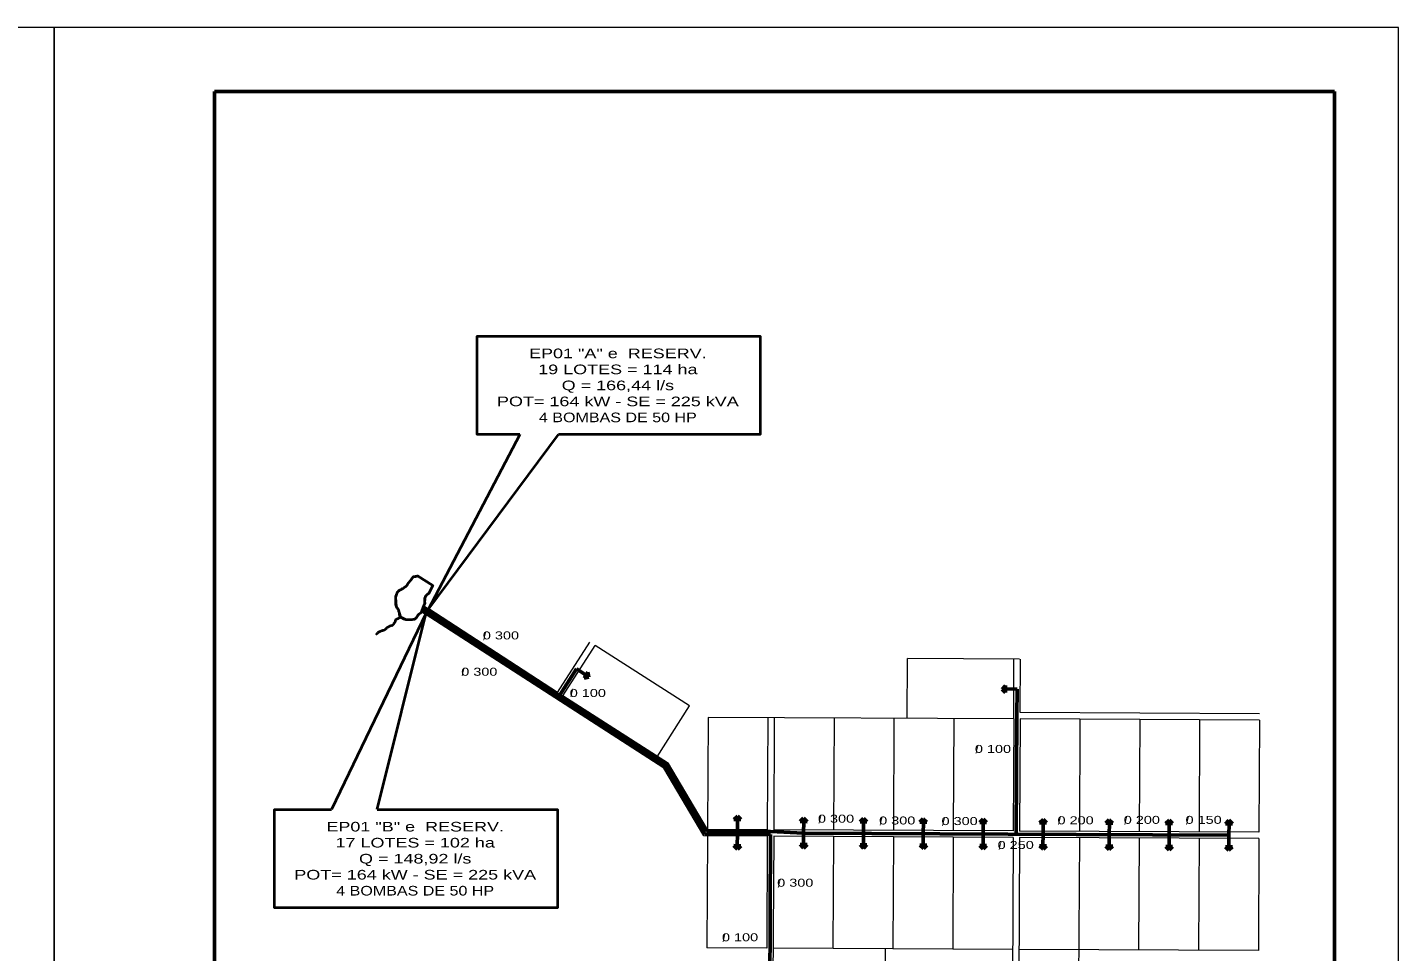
# Model space of a CAD drawing. Extents: x 312964 to 351929, y 9004151 to 9034973.
# Drawn here: x 347467 to 351751, y 9016114 to 9019001 of the extents above; entities that cross this region are included whole.
import ezdxf
from ezdxf.enums import TextEntityAlignment as Align

# ---------------------------------------------------------------- set-up
doc = ezdxf.new("R2010")
doc.units = 0
doc.header["$LTSCALE"] = 10
doc.layers.add('1', color=7, linetype='Continuous', lineweight=13)
doc.layers.add('2', color=7, linetype='Continuous', lineweight=53)

msp = doc.modelspace()

# ---------------------------------------------------------------- linework, layer by layer
at = {"layer": '1', "lineweight": 53}
for p, q in [((348050.92, 9018801.07), (348050.92, 9013261.07)), ((351550.92, 9018801.07), (348050.92, 9018801.07)), ((351550.92, 9013261.07), (351550.92, 9018801.07)), ((349137.41, 9016908.55), (348717.87, 9017180.57)), ((349132.01, 9016900.13), (348712.47, 9017172.15)), ((349128.99, 9016913.95), (349182.16, 9016996.86)), ((349212.23, 9016977.34), (349182.16, 9016996.86)), ((349206.5, 9016968.52), (349218.24, 9016986.6)), ((349221.41, 9016971.68), (349206.5, 9016968.52)), ((349221.41, 9016971.68), (349218.24, 9016986.6)), ((350512.16, 9016934.25), (350522.99, 9016944.98)), ((350512.16, 9016934.25), (350522.89, 9016923.42)), ((350522.99, 9016944.98), (350522.89, 9016923.42)), ((350522.94, 9016934.45), (350558.79, 9016934.28)), ((350558.38, 9016850.78), (350558.79, 9016934.28)), ((349466.48, 9016697.51), (349137.41, 9016908.55)), ((350558.38, 9016850.78), (350556.57, 9016480.78)), ((349588.76, 9016490.53), (349466.48, 9016697.51)), ((349685.08, 9016537.25), (349674.24, 9016526.52)), ((349685.08, 9016537.25), (349695.8, 9016526.42)), ((349695.8, 9016526.42), (349674.24, 9016526.52)), ((349685.28, 9016526.47), (349685.1, 9016490.62)), ((349892.05, 9016530.67), (349881.21, 9016519.94)), ((349902.77, 9016519.84), (349881.21, 9016519.94)), ((349892.05, 9016530.67), (349902.77, 9016519.84)), ((349892.25, 9016519.89), (349892.07, 9016484.04)), ((350079.04, 9016529.75), (350068.21, 9016519.03)), ((350089.77, 9016518.92), (350068.21, 9016519.03)), ((350079.04, 9016529.75), (350089.77, 9016518.92)), ((350079.25, 9016518.97), (350079.07, 9016483.12)), ((350266.04, 9016528.84), (350255.21, 9016518.11)), ((350276.77, 9016518), (350255.21, 9016518.11)), ((350266.04, 9016528.84), (350276.77, 9016518)), ((350266.25, 9016518.06), (350266.07, 9016482.21)), ((350453.04, 9016527.92), (350442.21, 9016517.19)), ((350463.76, 9016517.09), (350442.21, 9016517.19)), ((350453.04, 9016527.92), (350463.76, 9016517.09)), ((350453.24, 9016517.14), (350453.07, 9016481.29)), ((350640.04, 9016527), (350629.2, 9016516.28)), ((350650.76, 9016516.17), (350629.2, 9016516.28)), ((350640.04, 9016527), (350650.76, 9016516.17)), ((350640.24, 9016516.22), (350640.06, 9016480.37)), ((350847.03, 9016525.99), (350836.2, 9016515.26)), ((350857.76, 9016515.15), (350836.2, 9016515.26)), ((350847.03, 9016525.99), (350857.76, 9016515.15)), ((350847.24, 9016515.21), (350847.06, 9016479.36)), ((351034.03, 9016525.07), (351023.2, 9016514.34)), ((351044.76, 9016514.24), (351023.2, 9016514.34)), ((351034.03, 9016525.07), (351044.76, 9016514.24)), ((351034.24, 9016514.29), (351034.06, 9016478.44)), ((351221.03, 9016524.15), (351210.2, 9016513.43)), ((351231.76, 9016513.32), (351210.2, 9016513.43)), ((351221.03, 9016524.15), (351231.76, 9016513.32)), ((351221.24, 9016513.37), (351221.06, 9016477.53)), ((349788.55, 9016479.55), (349583.04, 9016480.56)), ((349788.6, 9016489.55), (349588.76, 9016490.53)), ((349684.88, 9016444.93), (349685.06, 9016480.78)), ((349892.07, 9016484.04), (349788.6, 9016489.55)), ((349891.9, 9016448.19), (349892.07, 9016484.04)), ((350743.56, 9016479.87), (349892.07, 9016484.04)), ((350078.89, 9016447.28), (350079.07, 9016483.12)), ((350265.89, 9016446.36), (350266.07, 9016482.21)), ((350452.89, 9016445.44), (350453.07, 9016481.29)), ((350639.89, 9016444.53), (350640.06, 9016480.37)), ((351221.06, 9016477.53), (350743.56, 9016479.87)), ((350846.89, 9016443.51), (350847.06, 9016479.36)), ((351033.88, 9016442.59), (351034.06, 9016478.44)), ((351220.88, 9016441.68), (351221.06, 9016477.53)), ((349674.36, 9016444.98), (349695.92, 9016444.87)), ((349685.08, 9016434.15), (349674.36, 9016444.98)), ((349685.08, 9016434.15), (349695.92, 9016444.87)), ((349881.38, 9016448.24), (349902.93, 9016448.14)), ((349892.1, 9016437.41), (349881.38, 9016448.24)), ((349892.1, 9016437.41), (349902.93, 9016448.14)), ((350068.37, 9016447.33), (350089.93, 9016447.22)), ((350079.1, 9016436.5), (350068.37, 9016447.33)), ((350079.1, 9016436.5), (350089.93, 9016447.22)), ((350255.37, 9016446.41), (350276.93, 9016446.3)), ((350266.1, 9016435.58), (350255.37, 9016446.41)), ((350266.1, 9016435.58), (350276.93, 9016446.3)), ((350442.37, 9016445.49), (350463.93, 9016445.39)), ((350453.1, 9016434.66), (350442.37, 9016445.49)), ((350453.1, 9016434.66), (350463.93, 9016445.39)), ((350629.37, 9016444.58), (350650.93, 9016444.47)), ((350640.09, 9016433.75), (350629.37, 9016444.58)), ((350640.09, 9016433.75), (350650.93, 9016444.47)), ((350836.36, 9016443.56), (350857.92, 9016443.46)), ((350847.09, 9016432.73), (350836.36, 9016443.56)), ((350847.09, 9016432.73), (350857.92, 9016443.46)), ((351023.36, 9016442.65), (351044.92, 9016442.54)), ((351034.09, 9016431.81), (351023.36, 9016442.65)), ((351034.09, 9016431.81), (351044.92, 9016442.54)), ((351210.36, 9016441.73), (351231.92, 9016441.62)), ((351221.09, 9016430.9), (351210.36, 9016441.73)), ((351221.09, 9016430.9), (351231.92, 9016441.62))]:
    msp.add_line(p, q, dxfattribs=at)
at = {"layer": '1', "lineweight": 40}
for p, q in [((348686.16, 9017287.63), (348733.17, 9017257.22)), ((348698.47, 9017177.95), (348719.14, 9017182.72)), ((348706.42, 9017190.67), (348711.2, 9017170)), ((348712.43, 9017171.97), (348720.37, 9017184.7))]:
    msp.add_line(p, q, dxfattribs=at)
at = {"layer": '1'}
for points in [[(343350.92, 9019001.07), (343350.92, 9013061.07), (347550.92, 9013061.07), (347550.92, 9019001.07)], [(347550.92, 9019001.07), (347550.92, 9013061.07), (351750.92, 9013061.07), (351750.92, 9019001.07)]]:
    msp.add_lwpolyline(points, close=True, dxfattribs=at)
at = {"layer": '1', "lineweight": 40}
for points in [[(348633.15, 9017158.29), (348627.76, 9017179.39), (348620.03, 9017191.34), (348618.16, 9017221.59), (348623.08, 9017236.59), (348631.04, 9017244.56), (348636.66, 9017246.44), (348651.65, 9017256.28), (348661.73, 9017270.58), (348673.67, 9017285.82), (348686.16, 9017287.63), (348733.17, 9017257.22), (348720.05, 9017231.9), (348716.77, 9017230.49), (348709.75, 9017222.06), (348707.87, 9017206.35), (348707.4, 9017199.08), (348704.59, 9017193.92), (348696.16, 9017171.89), (348688.43, 9017166.96), (348681.4, 9017156.18), (348675.31, 9017151.73), (348657.74, 9017150.32), (348647.91, 9017151.26)], [(348711.2, 9017170), (348719.14, 9017182.72), (348706.42, 9017190.67), (348698.47, 9017177.95)]]:
    msp.add_lwpolyline(points, close=True, dxfattribs=at)
for points in [[(348653.53, 9017258.63), (348653.53, 9017259.1), (348654, 9017260.03), (348654, 9017260.97), (348654.93, 9017261.91), (348655.4, 9017263.32), (348655.87, 9017263.32), (348656.34, 9017264.25), (348656.34, 9017264.72), (348656.81, 9017264.72), (348657.74, 9017266.13), (348660.56, 9017268.94), (348662.9, 9017272.22), (348666.65, 9017276.44), (348669.46, 9017280.19), (348670.86, 9017283.01), (348672.27, 9017284.41), (348672.74, 9017285.35), (348673.2, 9017285.82), (348673.67, 9017285.82), (348674.14, 9017285.82), (348676.02, 9017285.82), (348679.3, 9017286.29), (348683.98, 9017286.76), (348686.16, 9017287.63)], [(348689.13, 9017167.2), (348687.73, 9017166.73), (348687.26, 9017165.79), (348686.32, 9017164.85), (348684.92, 9017161.1), (348683.51, 9017159.7), (348682.11, 9017157.35), (348680.7, 9017155.01), (348679.3, 9017154.07), (348678.36, 9017153.13), (348677.89, 9017152.66), (348677.42, 9017152.66), (348677.42, 9017152.19), (348676.48, 9017152.19), (348676.02, 9017151.73), (348674.61, 9017151.73), (348673.67, 9017151.26), (348672.27, 9017151.26), (348669.46, 9017150.79), (348666.18, 9017150.79), (348662.9, 9017150.32), (348661.96, 9017150.32), (348661.02, 9017150.32), (348660.56, 9017150.32), (348657.74, 9017150.32), (348654, 9017150.32), (348650.72, 9017150.32), (348649.78, 9017150.32), (348649.31, 9017150.32), (348647.91, 9017151.26), (348646.03, 9017151.73), (348643.22, 9017152.19), (348641.35, 9017153.6), (348639.94, 9017154.07), (348639.01, 9017155.01), (348637.6, 9017155.95), (348635.73, 9017156.88), (348633.85, 9017157.82), (348632.45, 9017158.76), (348631.51, 9017159.7), (348631.51, 9017160.16), (348631.04, 9017161.1), (348630.57, 9017162.98), (348630.1, 9017163.92), (348629.64, 9017165.79), (348629.64, 9017167.2), (348629.64, 9017169.07), (348629.64, 9017170.48), (348629.17, 9017172.36), (348628.7, 9017174.7), (348627.76, 9017177.04), (348627.76, 9017179.39), (348626.82, 9017181.26), (348625.89, 9017182.67), (348624.95, 9017183.61), (348624.48, 9017184.55), (348624.01, 9017185.48), (348623.08, 9017186.42), (348622.14, 9017187.36), (348621.2, 9017188.77), (348620.27, 9017190.64), (348619.8, 9017192.05), (348619.33, 9017194.39), (348618.39, 9017198.61), (348617.92, 9017203.77), (348617.92, 9017209.4), (348617.92, 9017214.55), (348617.92, 9017218.77), (348618.39, 9017224.4), (348619.8, 9017228.62), (348620.73, 9017231.43), (348621.67, 9017232.84), (348622.14, 9017235.18), (348623.08, 9017236.59), (348624.48, 9017238.47), (348625.89, 9017239.87), (348627.76, 9017241.28), (348628.7, 9017242.69), (348629.64, 9017243.62), (348631.04, 9017244.56), (348634.32, 9017245.5), (348636.19, 9017245.97), (348637.13, 9017246.91), (348639.01, 9017247.84), (348640.41, 9017248.78), (348642.28, 9017249.25), (348643.22, 9017250.19), (348643.69, 9017251.12), (348644.16, 9017251.59), (348645.1, 9017252.06), (348646.03, 9017252.53), (348646.5, 9017253.47), (348648.37, 9017253.94), (348648.84, 9017254.88), (348650.72, 9017255.34), (348651.65, 9017256.28), (348652.59, 9017256.75), (348652.59, 9017257.22), (348653.06, 9017257.69), (348653.06, 9017258.16), (348653.53, 9017258.63)], [(348733.17, 9017257.22), (348731.77, 9017254.88), (348730.83, 9017252.53), (348728.95, 9017250.19), (348727.55, 9017246.44), (348726.61, 9017244.56), (348725.68, 9017242.69), (348724.74, 9017241.28), (348724.74, 9017239.87), (348724.27, 9017238.93), (348723.8, 9017238.47), (348723.33, 9017237.53), (348722.86, 9017237.06), (348722.86, 9017236.12), (348722.4, 9017235.18), (348721.46, 9017233.78), (348720.99, 9017232.37), (348720.52, 9017231.9), (348720.05, 9017231.9), (348719.58, 9017231.9), (348719.12, 9017231.43), (348718.65, 9017230.96), (348717.71, 9017230.96), (348716.77, 9017230.49), (348715.84, 9017229.56), (348715.37, 9017229.09), (348714.43, 9017228.15), (348713.96, 9017227.68), (348713.03, 9017226.74), (348712.56, 9017226.27), (348711.62, 9017225.34), (348710.68, 9017224.4), (348709.75, 9017222.06), (348709.28, 9017219.71), (348708.34, 9017218.77), (348707.87, 9017217.37), (348707.4, 9017215.96), (348707.4, 9017215.02), (348707.4, 9017214.08), (348707.4, 9017213.15), (348707.4, 9017212.68), (348707.4, 9017212.21), (348707.4, 9017211.27), (348707.4, 9017210.8), (348707.4, 9017210.33), (348707.4, 9017209.86), (348707.87, 9017209.4), (348707.87, 9017208.93), (348707.87, 9017208.46), (348707.87, 9017207.05), (348707.87, 9017205.64), (348708.34, 9017204.24), (348708.34, 9017202.36), (348708.34, 9017201.43), (348708.34, 9017200.49), (348708.34, 9017200.02), (348707.87, 9017199.55), (348707.4, 9017199.08), (348706.47, 9017197.67), (348706, 9017196.74), (348705.06, 9017194.86), (348704.12, 9017192.99), (348703.66, 9017191.58), (348703.66, 9017190.64), (348703.19, 9017189.7), (348703.19, 9017189.23), (348703.19, 9017188.77), (348703.19, 9017188.3), (348702.72, 9017187.83), (348702.72, 9017186.89), (348702.25, 9017185.95), (348702.25, 9017185.01), (348701.78, 9017185.01), (348701.31, 9017184.55), (348701.31, 9017184.08), (348701.31, 9017183.61), (348701.31, 9017183.14), (348700.85, 9017182.2), (348700.85, 9017181.73), (348700.38, 9017181.26), (348700.38, 9017180.33), (348700.38, 9017179.86), (348700.38, 9017179.39), (348699.91, 9017177.98), (348699.44, 9017177.04), (348699.44, 9017176.11), (348698.97, 9017175.17), (348698.03, 9017174.23), (348698.03, 9017173.76), (348697.57, 9017173.76), (348697.1, 9017173.29), (348697.1, 9017172.82), (348696.16, 9017171.89), (348695.69, 9017171.42), (348695.22, 9017170.95), (348694.29, 9017170.48), (348693.35, 9017170.01), (348692.41, 9017169.07), (348691.48, 9017168.6), (348690.54, 9017168.14), (348689.13, 9017167.2)], [(348560.07, 9016557.55), (348712.47, 9017172.15), (348416.79, 9016557.55)], [(348630.57, 9017158.29), (348630.57, 9017157.82), (348630.1, 9017157.35), (348629.17, 9017156.41), (348627.76, 9017155.95), (348626.82, 9017155.01), (348625.42, 9017154.07), (348624.95, 9017153.6), (348623.55, 9017153.13), (348622.61, 9017153.13), (348622.14, 9017153.13), (348620.73, 9017152.66), (348618.86, 9017151.73), (348617.92, 9017151.26), (348616.99, 9017150.32), (348616.99, 9017149.85), (348616.52, 9017148.91), (348616.52, 9017148.44), (348616.05, 9017147.97), (348616.05, 9017147.51), (348616.05, 9017146.57), (348615.58, 9017146.1), (348615.58, 9017145.16), (348615.11, 9017143.29), (348613.71, 9017140.94), (348612.3, 9017140), (348611.36, 9017139.07), (348610.9, 9017138.13), (348610.43, 9017137.19), (348610.43, 9017136.25), (348609.96, 9017135.32), (348609.49, 9017135.32), (348609.49, 9017134.85), (348609.02, 9017134.85), (348608.55, 9017134.38), (348607.62, 9017133.44), (348606.21, 9017132.5), (348604.81, 9017132.03), (348602.93, 9017131.56), (348601.53, 9017131.56), (348600.59, 9017131.1), (348600.12, 9017131.1), (348599.65, 9017130.63), (348598.72, 9017130.63), (348598.25, 9017130.16), (348597.78, 9017129.69), (348596.84, 9017129.69), (348595.9, 9017129.22), (348594.97, 9017128.75), (348594.03, 9017127.81), (348593.09, 9017127.34), (348592.16, 9017126.41), (348591.69, 9017125.94), (348590.28, 9017125), (348588.88, 9017124.06), (348588.41, 9017123.59), (348587, 9017122.66), (348585.6, 9017121.25), (348584.66, 9017119.84), (348583.72, 9017118.9), (348583.26, 9017118.9), (348582.79, 9017118.9), (348582.32, 9017117.97), (348581.85, 9017117.97), (348580.44, 9017117.5), (348579.51, 9017117.03), (348578.1, 9017117.03), (348577.17, 9017117.03), (348576.7, 9017117.03), (348576.7, 9017116.56), (348574.82, 9017116.09), (348572.95, 9017115.62), (348572.01, 9017115.15), (348571.07, 9017114.68), (348570.61, 9017114.22), (348569.67, 9017113.75), (348568.73, 9017113.75), (348566.86, 9017112.81), (348564.98, 9017112.34), (348563.58, 9017111.87), (348562.17, 9017110.93), (348561.24, 9017110), (348560.77, 9017109.53), (348560.77, 9017109.06), (348560.77, 9017108.59), (348559.36, 9017107.18), (348558.43, 9017106.25), (348557.49, 9017105.78), (348557.49, 9017105.31), (348557.49, 9017105.78)]]:
    msp.add_lwpolyline(points, dxfattribs=at)
at = {"layer": '1', "lineweight": 53}
for points in [[(349583.04, 9016480.56), (349459.08, 9016690.38), (349132.01, 9016900.13)], [(349788.55, 9016479.55), (349784.93, 9015740.56), (349781.46, 9015032.87)]]:
    msp.add_lwpolyline(points, dxfattribs=at)
at = {"layer": '2', "lineweight": 13}
for p, q in [((349123.27, 9016923.56), (348720.57, 9017184.78)), ((349455.38, 9016686.81), (348709.77, 9017167.94)), ((349123.27, 9016923.56), (349224.22, 9017080.97)), ((349140.11, 9016912.76), (349241.05, 9017070.17)), ((349535.68, 9016881.23), (349241.05, 9017070.17)), ((350215.33, 9016842.46), (350216.25, 9017029.46)), ((350566.25, 9017027.74), (350216.25, 9017029.46)), ((350548.33, 9016840.83), (350549.25, 9017027.83)), ((350568.43, 9016860.73), (350569.25, 9017027.73)), ((349470.18, 9016701.08), (349140.11, 9016912.76)), ((349434.1, 9016722.84), (349535.68, 9016881.23)), ((349593.34, 9016845.51), (349591.63, 9016495.51)), ((350548.33, 9016840.83), (349593.34, 9016845.51)), ((349780.34, 9016844.59), (349778.62, 9016494.6)), ((349800.34, 9016844.5), (349798.62, 9016494.5)), ((349987.34, 9016843.58), (349985.62, 9016493.58)), ((350174.34, 9016842.66), (350172.62, 9016492.67)), ((350361.33, 9016841.74), (350359.62, 9016491.75)), ((350548.33, 9016840.83), (350546.62, 9016490.83)), ((350568.33, 9016840.73), (350566.61, 9016490.73)), ((351316.32, 9016837.06), (350568.33, 9016840.73)), ((351316.42, 9016857.06), (350568.43, 9016860.73)), ((350755.33, 9016839.81), (350753.61, 9016489.82)), ((350755.33, 9016839.81), (350753.61, 9016489.82)), ((350942.33, 9016838.9), (350940.61, 9016488.9)), ((351129.32, 9016837.98), (351127.61, 9016487.98)), ((351316.32, 9016837.06), (351314.61, 9016487.07)), ((349580.18, 9016475.57), (349455.38, 9016686.81)), ((349591.63, 9016495.51), (349470.18, 9016701.08)), ((349778.62, 9016494.6), (349591.63, 9016495.51)), ((350546.62, 9016490.83), (349798.62, 9016494.5)), ((349778.53, 9016474.6), (349580.18, 9016475.57)), ((349591.53, 9016475.51), (349589.81, 9016125.52)), ((349778.53, 9016474.6), (349776.81, 9016124.6)), ((349798.53, 9016474.5), (349794.98, 9015750.51)), ((350546.52, 9016470.83), (349798.53, 9016474.5)), ((349985.52, 9016473.58), (349983.81, 9016123.59)), ((350172.52, 9016472.67), (350170.81, 9016122.67)), ((350359.52, 9016471.75), (350357.8, 9016121.75)), ((350546.52, 9016470.83), (350543.09, 9015772.11)), ((350566.52, 9016470.73), (350563.09, 9015770.74)), ((351314.51, 9016467.07), (350566.52, 9016470.73)), ((351314.61, 9016487.07), (350566.61, 9016490.73)), ((350753.51, 9016469.82), (350748.27, 9015399.83)), ((350753.51, 9016469.82), (350750.08, 9015769.83)), ((350940.51, 9016468.9), (350938.8, 9016118.91)), ((351127.51, 9016467.98), (351125.79, 9016117.99)), ((351314.51, 9016467.07), (351312.79, 9016117.07)), ((349776.81, 9016124.6), (349589.81, 9016125.52)), ((350544.8, 9016120.84), (349796.81, 9016124.5)), ((350146.81, 9016122.79), (350144.97, 9015748.79)), ((351312.79, 9016117.07), (350564.8, 9016120.74))]:
    msp.add_line(p, q, dxfattribs=at)
at = {"layer": '2', "lineweight": 40}
for points in [[(348872.48, 9017962.72), (348872.48, 9018036.13), (349049.97, 9018036.13)], [(349049.97, 9018036.13), (349756.71, 9018036.13), (349756.71, 9017729.3), (349125.71, 9017729.3)], [(349005.78, 9017729.3), (348872.48, 9017729.3), (348872.48, 9017962.72)], [(349005.78, 9017729.3), (348717.87, 9017180.57), (349125.71, 9017729.3)], [(348239.3, 9016484.14), (348239.3, 9016557.55), (348416.79, 9016557.55)], [(348560.07, 9016557.55), (349123.53, 9016557.55), (349123.53, 9016250.72), (348492.53, 9016250.72)], [(348492.53, 9016250.72), (348239.3, 9016250.72), (348239.3, 9016484.14)]]:
    msp.add_lwpolyline(points, dxfattribs=at)

# ---------------------------------------------------------------- texts
at = {"layer": '1'}
for p in [(348895.88, 9017087.06), (348828.35, 9016975.1), (349168.03, 9016909.51), (350433.57, 9016732.36), (349943.25, 9016514.48), (350134.39, 9016508.85), (350691.7, 9016510.76), (350898.68, 9016510.76), (351091.7, 9016510.76), (350329.28, 9016506.98), (350505.97, 9016432.42), (349815.84, 9016314.36), (349643.4, 9016143.96)]:
    msp.add_text('/', height=25, dxfattribs=at).set_placement(p, align=Align.CENTER)
at = {"layer": '1', "width": 1.35}
for s, p in [('0 300', (348946.33, 9017089.25)), ('0 300', (348878.8, 9016975.76)), ('0 100', (349217.86, 9016909.36)), ('0 100', (350483.67, 9016734.63)), ('0 300', (349993.36, 9016516.75)), ('0 300', (350184.5, 9016511.12)), ('0 200', (350741.8, 9016511.69)), ('0 200', (350948.79, 9016513.03)), ('0 150', (351141.8, 9016513.03)), ('0 300', (350379.39, 9016509.25)), ('0 250', (350554.75, 9016434.69)), ('0 300', (349865.95, 9016316.62)), ('0 100', (349693.51, 9016146.23))]:
    msp.add_text(s, height=25, dxfattribs=at).set_placement(p, align=Align.CENTER)
at = {"layer": '2'}
for s, width, p in [('EP01 "A" e  RESERV.', 1.4, (349311.66, 9017967.79)), ('19 LOTES = 114 ha', 1.4, (349311.66, 9017917.79)), ('Q = 166,44 l/s', 1.4, (349311.66, 9017867.79)), ('POT= 164 kW - SE = 225 kVA', 1.4, (349311.66, 9017817.79)), ('4 BOMBAS DE 50 HP', 1.25, (349311.66, 9017767.79)), ('EP01 "B" e  RESERV.', 1.4, (348678.47, 9016489.21)), ('17 LOTES = 102 ha', 1.4, (348678.47, 9016439.21)), ('Q = 148,92 l/s', 1.4, (348678.47, 9016389.21)), ('POT= 164 kW - SE = 225 kVA', 1.4, (348678.47, 9016339.21)), ('4 BOMBAS DE 50 HP', 1.25, (348678.47, 9016289.21))]:
    msp.add_text(s, height=30, dxfattribs=dict(at, width=width)).set_placement(p, align=Align.CENTER)

doc.saveas('drawing.dxf')
